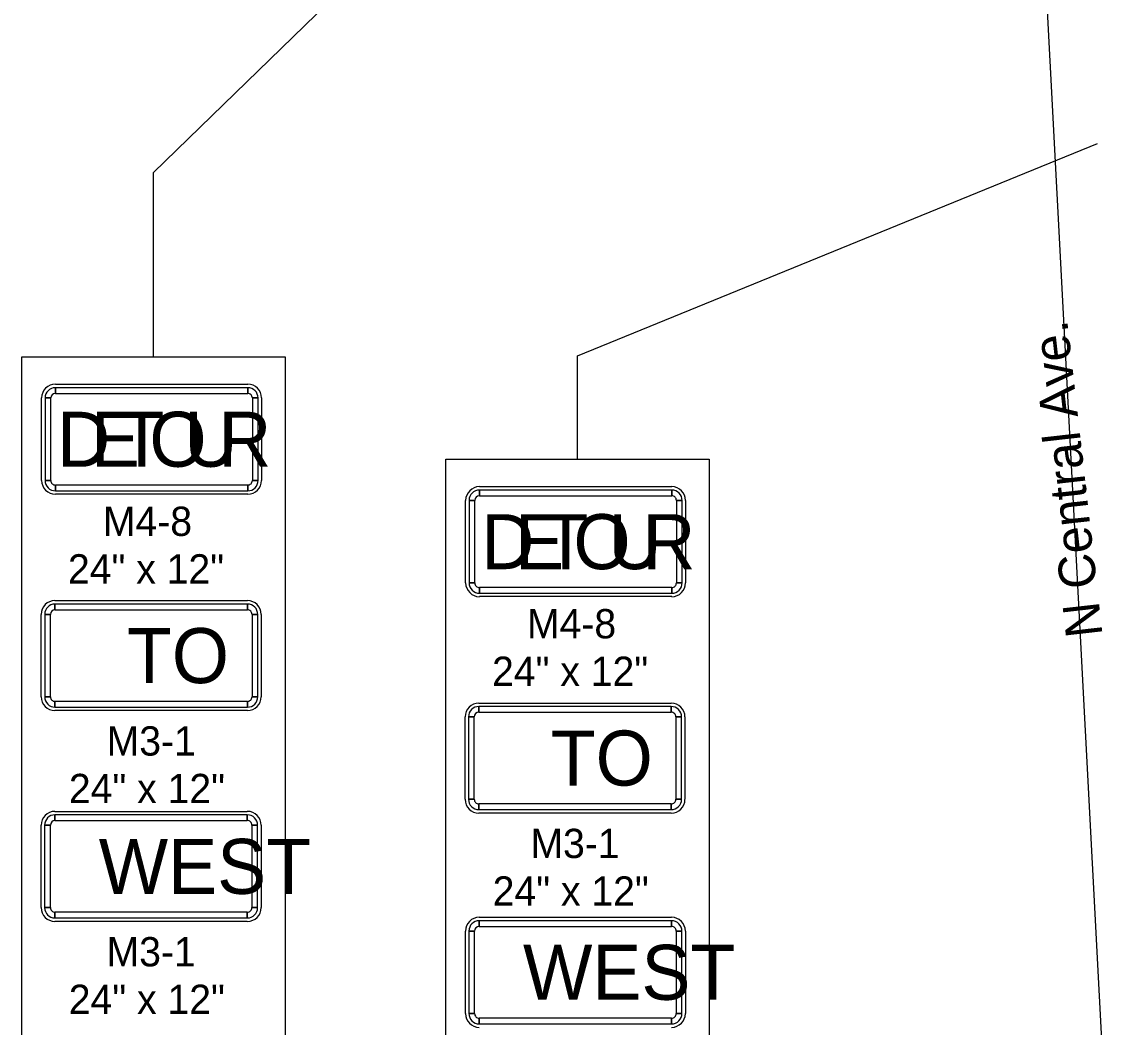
# Model space of a CAD drawing. Extents: x 10133 to 81668, y 6132 to 11018.
# Drawn here: x 10520.3 to 10816.6, y 8659.2 to 8934 of the extents above; entities that cross this region are included whole.
import ezdxf

# ---------------------------------------------------------------- set-up
doc = ezdxf.new("R2010")
doc.units = 0
for name, color, linetype in [('dsnTextFinalPlan', 7, 'Continuous'), ('Level 10', 7, 'Continuous'), ('Level 2', 7, 'Continuous'), ('Level 5', 7, 'Continuous')]:
    doc.layers.add(name, color=color, linetype=linetype)

msp = doc.modelspace()

# ---------------------------------------------------------------- linework, layer by layer
at = {"layer": 'dsnTextFinalPlan'}
for p, q in [((10672.27, 8842.69), (10814.4, 8900.7)), ((10672.27, 8814.46), (10672.27, 8842.69))]:
    msp.add_line(p, q, dxfattribs=at)
for points in [[(10785.14, 9142), (10794.64, 9051.15), (10817.78, 8612.5)], [(10556.31, 8842.44), (10556.31, 8892.79), (10801.13, 9130.54)]]:
    msp.add_lwpolyline(points, dxfattribs=at)
for points in [[(10520.28, 8842.44), (10592.34, 8842.44), (10592.34, 8530.22), (10520.28, 8530.22)], [(10520.28, 8842.44), (10592.34, 8842.44), (10592.34, 8530.22), (10520.28, 8530.22)], [(10520.28, 8842.44), (10592.34, 8842.44), (10592.34, 8530.22), (10520.28, 8530.22)], [(10636.23, 8814.46), (10708.3, 8814.46), (10708.3, 8502.24), (10636.23, 8502.24)], [(10636.23, 8814.46), (10708.3, 8814.46), (10708.3, 8502.24), (10636.23, 8502.24)]]:
    msp.add_lwpolyline(points, close=True, dxfattribs=at)
at = {"layer": 'Level 10'}
for p, q in [((10529.49, 8834.93), (10582.1, 8834.93)), ((10529.49, 8834.93), (10582.1, 8834.93)), ((10529.49, 8832.43), (10529.49, 8833.99)), ((10529.49, 8832.43), (10529.49, 8833.99)), ((10582.1, 8833.99), (10582.1, 8832.43)), ((10582.1, 8833.99), (10582.1, 8832.43)), ((10525.73, 8808.63), (10525.73, 8831.18)), ((10525.73, 8808.63), (10525.73, 8831.18)), ((10526.67, 8831.18), (10528.23, 8831.18)), ((10526.67, 8831.18), (10528.23, 8831.18)), ((10583.35, 8831.18), (10584.92, 8831.18)), ((10583.35, 8831.18), (10584.92, 8831.18)), ((10585.86, 8831.18), (10585.86, 8808.63)), ((10585.86, 8831.18), (10585.86, 8808.63)), ((10528.23, 8808.63), (10526.67, 8808.63)), ((10528.23, 8808.63), (10526.67, 8808.63)), ((10529.49, 8805.81), (10529.49, 8807.37)), ((10529.49, 8805.81), (10529.49, 8807.37)), ((10582.1, 8807.37), (10582.1, 8805.81)), ((10582.1, 8807.37), (10582.1, 8805.81)), ((10584.92, 8808.63), (10583.35, 8808.63)), ((10584.92, 8808.63), (10583.35, 8808.63)), ((10645.44, 8806.95), (10698.05, 8806.95)), ((10582.1, 8804.87), (10529.49, 8804.87)), ((10582.1, 8804.87), (10529.49, 8804.87)), ((10645.44, 8804.45), (10645.44, 8806.01)), ((10698.05, 8806.01), (10698.05, 8804.45)), ((10641.68, 8780.64), (10641.68, 8803.19)), ((10642.62, 8803.19), (10644.19, 8803.19)), ((10699.31, 8803.19), (10700.87, 8803.19)), ((10701.81, 8803.19), (10701.81, 8780.64)), ((10644.19, 8780.64), (10642.62, 8780.64)), ((10700.87, 8780.64), (10699.31, 8780.64)), ((10645.44, 8777.83), (10645.44, 8779.39)), ((10698.05, 8776.89), (10645.44, 8776.89)), ((10698.05, 8779.39), (10698.05, 8777.83)), ((10529.39, 8775.81), (10582.01, 8775.81)), ((10529.39, 8775.81), (10582.01, 8775.81)), ((10529.39, 8773.31), (10529.39, 8774.87)), ((10529.39, 8773.31), (10529.39, 8774.87)), ((10582.01, 8774.87), (10582.01, 8773.31)), ((10582.01, 8774.87), (10582.01, 8773.31)), ((10525.64, 8749.51), (10525.64, 8772.05)), ((10525.64, 8749.51), (10525.64, 8772.05)), ((10526.58, 8772.05), (10528.14, 8772.05)), ((10526.58, 8772.05), (10528.14, 8772.05)), ((10583.26, 8772.05), (10584.82, 8772.05)), ((10583.26, 8772.05), (10584.82, 8772.05)), ((10585.76, 8772.05), (10585.76, 8749.51)), ((10585.76, 8772.05), (10585.76, 8749.51)), ((10528.14, 8749.51), (10526.58, 8749.51)), ((10528.14, 8749.51), (10526.58, 8749.51)), ((10529.39, 8746.69), (10529.39, 8748.25)), ((10529.39, 8746.69), (10529.39, 8748.25)), ((10582.01, 8748.25), (10582.01, 8746.69)), ((10582.01, 8748.25), (10582.01, 8746.69)), ((10584.82, 8749.51), (10583.26, 8749.51)), ((10584.82, 8749.51), (10583.26, 8749.51)), ((10645.28, 8747.81), (10697.89, 8747.81)), ((10582.01, 8745.75), (10529.39, 8745.75)), ((10582.01, 8745.75), (10529.39, 8745.75)), ((10641.52, 8721.5), (10641.52, 8744.05)), ((10642.46, 8744.05), (10644.03, 8744.05)), ((10645.28, 8745.3), (10645.28, 8746.87)), ((10697.89, 8746.87), (10697.89, 8745.3)), ((10699.14, 8744.05), (10700.71, 8744.05)), ((10701.65, 8744.05), (10701.65, 8721.5)), ((10644.03, 8721.5), (10642.46, 8721.5)), ((10700.71, 8721.5), (10699.14, 8721.5)), ((10529.37, 8718.21), (10581.98, 8718.21)), ((10529.37, 8718.21), (10581.98, 8718.21)), ((10645.28, 8718.68), (10645.28, 8720.25)), ((10697.89, 8717.74), (10645.28, 8717.74)), ((10697.89, 8720.25), (10697.89, 8718.68)), ((10525.61, 8691.9), (10525.61, 8714.45)), ((10525.61, 8691.9), (10525.61, 8714.45)), ((10526.55, 8714.45), (10528.12, 8714.45)), ((10526.55, 8714.45), (10528.12, 8714.45)), ((10529.37, 8715.7), (10529.37, 8717.27)), ((10529.37, 8715.7), (10529.37, 8717.27)), ((10581.98, 8717.27), (10581.98, 8715.7)), ((10581.98, 8717.27), (10581.98, 8715.7)), ((10583.24, 8714.45), (10584.8, 8714.45)), ((10583.24, 8714.45), (10584.8, 8714.45)), ((10585.74, 8714.45), (10585.74, 8691.9)), ((10585.74, 8714.45), (10585.74, 8691.9)), ((10528.12, 8691.9), (10526.55, 8691.9)), ((10528.12, 8691.9), (10526.55, 8691.9)), ((10529.37, 8689.08), (10529.37, 8690.65)), ((10529.37, 8689.08), (10529.37, 8690.65)), ((10581.98, 8690.65), (10581.98, 8689.08)), ((10581.98, 8690.65), (10581.98, 8689.08)), ((10584.8, 8691.9), (10583.24, 8691.9)), ((10584.8, 8691.9), (10583.24, 8691.9)), ((10581.98, 8688.14), (10529.37, 8688.14)), ((10581.98, 8688.14), (10529.37, 8688.14)), ((10645.38, 8689.26), (10698, 8689.26)), ((10645.38, 8686.75), (10645.38, 8688.32)), ((10698, 8688.32), (10698, 8686.75)), ((10641.63, 8662.95), (10641.63, 8685.5)), ((10642.57, 8685.5), (10644.13, 8685.5)), ((10699.25, 8685.5), (10700.82, 8685.5)), ((10701.75, 8685.5), (10701.75, 8662.95)), ((10644.13, 8662.95), (10642.57, 8662.95)), ((10645.38, 8660.14), (10645.38, 8661.7)), ((10698, 8661.7), (10698, 8660.14)), ((10700.82, 8662.95), (10699.25, 8662.95))]:
    msp.add_line(p, q, dxfattribs=at)
for points in [[(10582.1, 8833.99), (10529.49, 8833.99), (10529.49, 8832.43), (10582.1, 8832.43), (10582.1, 8833.99)], [(10582.1, 8833.99), (10529.49, 8833.99), (10529.49, 8832.43), (10582.1, 8832.43), (10582.1, 8833.99)], [(10526.67, 8831.18), (10526.67, 8808.63), (10528.23, 8808.63), (10528.23, 8831.18), (10526.67, 8831.18)], [(10526.67, 8831.18), (10526.67, 8808.63), (10528.23, 8808.63), (10528.23, 8831.18), (10526.67, 8831.18)], [(10584.92, 8808.63), (10584.92, 8831.18), (10583.35, 8831.18), (10583.35, 8808.63), (10584.92, 8808.63)], [(10584.92, 8808.63), (10584.92, 8831.18), (10583.35, 8831.18), (10583.35, 8808.63), (10584.92, 8808.63)], [(10529.49, 8805.81), (10582.1, 8805.81), (10582.1, 8807.37), (10529.49, 8807.37), (10529.49, 8805.81)], [(10529.49, 8805.81), (10582.1, 8805.81), (10582.1, 8807.37), (10529.49, 8807.37), (10529.49, 8805.81)], [(10698.05, 8806.01), (10645.44, 8806.01), (10645.44, 8804.45), (10698.05, 8804.45), (10698.05, 8806.01)], [(10642.62, 8803.19), (10642.62, 8780.64), (10644.19, 8780.64), (10644.19, 8803.19), (10642.62, 8803.19)], [(10700.87, 8780.64), (10700.87, 8803.19), (10699.31, 8803.19), (10699.31, 8780.64), (10700.87, 8780.64)], [(10645.44, 8777.83), (10698.05, 8777.83), (10698.05, 8779.39), (10645.44, 8779.39), (10645.44, 8777.83)], [(10582.01, 8774.87), (10529.39, 8774.87), (10529.39, 8773.31), (10582.01, 8773.31), (10582.01, 8774.87)], [(10582.01, 8774.87), (10529.39, 8774.87), (10529.39, 8773.31), (10582.01, 8773.31), (10582.01, 8774.87)], [(10526.58, 8772.05), (10526.58, 8749.51), (10528.14, 8749.51), (10528.14, 8772.05), (10526.58, 8772.05)], [(10526.58, 8772.05), (10526.58, 8749.51), (10528.14, 8749.51), (10528.14, 8772.05), (10526.58, 8772.05)], [(10584.82, 8749.51), (10584.82, 8772.05), (10583.26, 8772.05), (10583.26, 8749.51), (10584.82, 8749.51)], [(10584.82, 8749.51), (10584.82, 8772.05), (10583.26, 8772.05), (10583.26, 8749.51), (10584.82, 8749.51)], [(10529.39, 8746.69), (10582.01, 8746.69), (10582.01, 8748.25), (10529.39, 8748.25), (10529.39, 8746.69)], [(10529.39, 8746.69), (10582.01, 8746.69), (10582.01, 8748.25), (10529.39, 8748.25), (10529.39, 8746.69)], [(10642.46, 8744.05), (10642.46, 8721.5), (10644.03, 8721.5), (10644.03, 8744.05), (10642.46, 8744.05)], [(10697.89, 8746.87), (10645.28, 8746.87), (10645.28, 8745.3), (10697.89, 8745.3), (10697.89, 8746.87)], [(10700.71, 8721.5), (10700.71, 8744.05), (10699.14, 8744.05), (10699.14, 8721.5), (10700.71, 8721.5)], [(10645.28, 8718.68), (10697.89, 8718.68), (10697.89, 8720.25), (10645.28, 8720.25), (10645.28, 8718.68)], [(10526.55, 8714.45), (10526.55, 8691.9), (10528.12, 8691.9), (10528.12, 8714.45), (10526.55, 8714.45)], [(10526.55, 8714.45), (10526.55, 8691.9), (10528.12, 8691.9), (10528.12, 8714.45), (10526.55, 8714.45)], [(10581.98, 8717.27), (10529.37, 8717.27), (10529.37, 8715.7), (10581.98, 8715.7), (10581.98, 8717.27)], [(10581.98, 8717.27), (10529.37, 8717.27), (10529.37, 8715.7), (10581.98, 8715.7), (10581.98, 8717.27)], [(10584.8, 8691.9), (10584.8, 8714.45), (10583.24, 8714.45), (10583.24, 8691.9), (10584.8, 8691.9)], [(10584.8, 8691.9), (10584.8, 8714.45), (10583.24, 8714.45), (10583.24, 8691.9), (10584.8, 8691.9)], [(10529.37, 8689.08), (10581.98, 8689.08), (10581.98, 8690.65), (10529.37, 8690.65), (10529.37, 8689.08)], [(10529.37, 8689.08), (10581.98, 8689.08), (10581.98, 8690.65), (10529.37, 8690.65), (10529.37, 8689.08)], [(10698, 8688.32), (10645.38, 8688.32), (10645.38, 8686.75), (10698, 8686.75), (10698, 8688.32)], [(10642.57, 8685.5), (10642.57, 8662.95), (10644.13, 8662.95), (10644.13, 8685.5), (10642.57, 8685.5)], [(10700.82, 8662.95), (10700.82, 8685.5), (10699.25, 8685.5), (10699.25, 8662.95), (10700.82, 8662.95)], [(10645.38, 8660.14), (10698, 8660.14), (10698, 8661.7), (10645.38, 8661.7), (10645.38, 8660.14)]]:
    msp.add_lwpolyline(points, close=True, dxfattribs=at)
for centre, radius, start, end in [((10529.49, 8831.18), 3.76, 90, 180), ((10529.49, 8831.18), 3.76, 90, 180), ((10529.49, 8831.18), 2.82, 90.0002, 179.9998), ((10529.49, 8831.18), 2.82, 90.0002, 179.9998), ((10582.1, 8831.18), 3.76, 0, 90), ((10582.1, 8831.18), 3.76, 0, 90), ((10582.1, 8831.18), 2.82, 0, 90.0002), ((10582.1, 8831.18), 2.82, 0, 90.0002), ((10529.49, 8831.18), 1.25, 90.0002, 179.9998), ((10529.49, 8831.18), 1.25, 90.0002, 179.9998), ((10582.1, 8831.18), 1.25, 0, 90.0002), ((10582.1, 8831.18), 1.25, 0, 90.0002), ((10529.49, 8808.63), 3.76, 180, 270), ((10529.49, 8808.63), 3.76, 180, 270), ((10529.49, 8808.63), 2.82, 179.9998, 270.0001), ((10529.49, 8808.63), 2.82, 179.9998, 270.0001), ((10529.49, 8808.63), 1.25, 179.9998, 270.0001), ((10529.49, 8808.63), 1.25, 179.9998, 270.0001), ((10582.1, 8808.63), 2.82, 270.0001, 0.0003), ((10582.1, 8808.63), 1.25, 270.0001, 0.0003), ((10582.1, 8808.63), 3.76, 270, 359.9911), ((10582.1, 8808.63), 2.82, 270.0001, 0.0003), ((10582.1, 8808.63), 1.25, 270.0001, 0.0003), ((10582.1, 8808.63), 3.76, 270, 359.9911), ((10645.44, 8803.19), 3.76, 90, 180), ((10698.05, 8803.19), 3.76, 0, 90), ((10645.44, 8803.19), 2.82, 90.0002, 179.9998), ((10645.44, 8803.19), 1.25, 90.0002, 179.9998), ((10698.05, 8803.19), 2.82, 0, 90.0002), ((10698.05, 8803.19), 1.25, 0, 90.0002), ((10645.44, 8780.64), 3.76, 180, 270), ((10645.44, 8780.64), 2.82, 179.9998, 270.0001), ((10645.44, 8780.64), 1.25, 179.9998, 270.0001), ((10698.05, 8780.64), 2.82, 270.0001, 0.0003), ((10698.05, 8780.64), 1.25, 270.0001, 0.0003), ((10698.05, 8780.64), 3.76, 270, 359.9911), ((10529.39, 8772.05), 3.76, 90, 180), ((10529.39, 8772.05), 3.76, 90, 180), ((10529.39, 8772.05), 2.82, 90.0002, 179.9998), ((10529.39, 8772.05), 2.82, 90.0002, 179.9998), ((10582.01, 8772.05), 3.76, 0, 90), ((10582.01, 8772.05), 3.76, 0, 90), ((10582.01, 8772.05), 2.82, 0, 90.0002), ((10582.01, 8772.05), 2.82, 0, 90.0002), ((10529.39, 8772.05), 1.25, 90.0002, 179.9998), ((10529.39, 8772.05), 1.25, 90.0002, 179.9998), ((10582.01, 8772.05), 1.25, 0, 90.0002), ((10582.01, 8772.05), 1.25, 0, 90.0002), ((10529.39, 8749.51), 3.76, 180, 270), ((10529.39, 8749.51), 3.76, 180, 270), ((10529.39, 8749.51), 2.82, 179.9998, 270.0001), ((10529.39, 8749.51), 2.82, 179.9998, 270.0001), ((10529.39, 8749.51), 1.25, 179.9998, 270.0001), ((10529.39, 8749.51), 1.25, 179.9998, 270.0001), ((10582.01, 8749.51), 2.82, 270.0001, 0.0003), ((10582.01, 8749.51), 1.25, 270.0001, 0.0003), ((10582.01, 8749.51), 3.76, 270, 359.9911), ((10582.01, 8749.51), 2.82, 270.0001, 0.0003), ((10582.01, 8749.51), 1.25, 270.0001, 0.0003), ((10582.01, 8749.51), 3.76, 270, 359.9911), ((10645.28, 8744.05), 3.76, 90, 180), ((10697.89, 8744.05), 3.76, 0, 90), ((10645.28, 8744.05), 2.82, 90.0002, 179.9998), ((10645.28, 8744.05), 1.25, 90.0002, 179.9998), ((10697.89, 8744.05), 2.82, 0, 90.0002), ((10697.89, 8744.05), 1.25, 0, 90.0002), ((10645.28, 8721.5), 3.76, 180, 270), ((10645.28, 8721.5), 2.82, 179.9998, 270.0001), ((10645.28, 8721.5), 1.25, 179.9998, 270.0001), ((10697.89, 8721.5), 2.82, 270.0001, 0.0003), ((10697.89, 8721.5), 1.25, 270.0001, 0.0003), ((10697.89, 8721.5), 3.76, 270, 359.9911), ((10529.37, 8714.45), 3.76, 90, 180), ((10529.37, 8714.45), 3.76, 90, 180), ((10581.98, 8714.45), 3.76, 0, 90), ((10581.98, 8714.45), 3.76, 0, 90), ((10529.37, 8714.45), 2.82, 90.0002, 179.9998), ((10529.37, 8714.45), 2.82, 90.0002, 179.9998), ((10529.37, 8714.45), 1.25, 90.0002, 179.9998), ((10529.37, 8714.45), 1.25, 90.0002, 179.9998), ((10581.98, 8714.45), 2.82, 0, 90.0002), ((10581.98, 8714.45), 2.82, 0, 90.0002), ((10581.98, 8714.45), 1.25, 0, 90.0002), ((10581.98, 8714.45), 1.25, 0, 90.0002), ((10529.37, 8691.9), 3.76, 180, 270), ((10529.37, 8691.9), 3.76, 180, 270), ((10529.37, 8691.9), 2.82, 179.9998, 270.0001), ((10529.37, 8691.9), 2.82, 179.9998, 270.0001), ((10529.37, 8691.9), 1.25, 179.9998, 270.0001), ((10529.37, 8691.9), 1.25, 179.9998, 270.0001), ((10581.98, 8691.9), 2.82, 270.0001, 0.0003), ((10581.98, 8691.9), 1.25, 270.0001, 0.0003), ((10581.98, 8691.9), 3.76, 270, 359.9911), ((10581.98, 8691.9), 2.82, 270.0001, 0.0003), ((10581.98, 8691.9), 1.25, 270.0001, 0.0003), ((10581.98, 8691.9), 3.76, 270, 359.9911), ((10645.38, 8685.5), 3.76, 90, 180), ((10645.38, 8685.5), 2.82, 90.0002, 179.9998), ((10698, 8685.5), 3.76, 0, 90), ((10698, 8685.5), 2.82, 0, 90.0002), ((10645.38, 8685.5), 1.25, 90.0002, 179.9998), ((10698, 8685.5), 1.25, 0, 90.0002), ((10645.38, 8662.95), 3.76, 180, 270), ((10645.38, 8662.95), 2.82, 179.9998, 270.0001), ((10645.38, 8662.95), 1.25, 179.9998, 270.0001), ((10698, 8662.95), 2.82, 270.0001, 0.0003), ((10698, 8662.95), 1.25, 270.0001, 0.0003), ((10698, 8662.95), 3.76, 270, 359.9911)]:
    msp.add_arc(centre, radius, start, end, dxfattribs=at)

# ---------------------------------------------------------------- texts
for s, height, p in [('D', 15.03, (10529.97, 8812.39)), ('D', 15.03, (10529.97, 8812.39)), ('E', 15.03, (10539.21, 8812.39)), ('E', 15.03, (10539.21, 8812.39)), ('T', 15.03, (10546.99, 8812.39)), ('T', 15.03, (10546.99, 8812.39)), ('O', 15.03, (10555.2, 8812.39)), ('O', 15.03, (10555.2, 8812.39)), ('U', 15.03, (10564.79, 8812.39)), ('U', 15.03, (10564.79, 8812.39)), ('R', 15.03, (10574.03, 8812.39)), ('R', 15.03, (10574.03, 8812.39)), ('D', 15.03, (10645.93, 8784.4)), ('E', 15.03, (10655.16, 8784.4)), ('T', 15.03, (10662.94, 8784.4)), ('O', 15.03, (10671.15, 8784.4)), ('U', 15.03, (10680.74, 8784.4)), ('R', 15.03, (10689.98, 8784.4)), ('TO', 15.032, (10549.06, 8753.26)), ('TO', 15.032, (10549.06, 8753.26)), ('TO', 15.032, (10664.94, 8725.26)), ('WEST', 15.032, (10541.35, 8695.66)), ('WEST', 15.032, (10657.36, 8666.71))]:
    msp.add_text(s, height=height, dxfattribs=at).set_placement(p)
at = {"layer": 'Level 2'}
msp.add_text('N Central Ave.', height=10, rotation=96.4177, dxfattribs=at).set_placement((10815.85, 8766.32))
at = {"layer": 'Level 5'}
for s, p in [('M4-8', (10542.49, 8793.48)), ('M4-8', (10542.49, 8793.48)), ('24" x 12"', (10532.94, 8780.48)), ('24" x 12"', (10532.94, 8780.48)), ('M4-8', (10658.45, 8765.5)), ('24" x 12"', (10648.9, 8752.5)), ('M3-1', (10543.52, 8733.46)), ('M3-1', (10543.52, 8733.46)), ('24" x 12"', (10533.19, 8720.46)), ('24" x 12"', (10533.19, 8720.46)), ('M3-1', (10659.4, 8705.45)), ('24" x 12"', (10649.07, 8692.45)), ('M3-1', (10543.5, 8675.85)), ('M3-1', (10543.5, 8675.85)), ('24" x 12"', (10533.16, 8662.85)), ('24" x 12"', (10533.16, 8662.85))]:
    msp.add_text(s, height=8, dxfattribs=at).set_placement(p)

doc.saveas('drawing.dxf')
